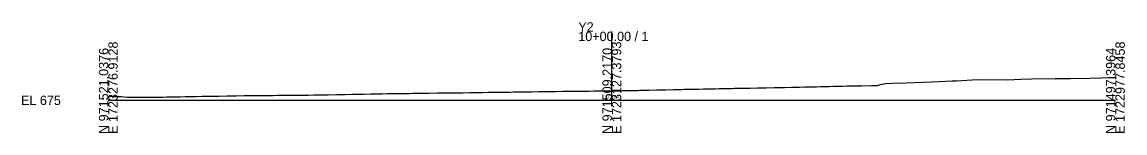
# Model space of a CAD drawing. Extents: x -26 to 303, y -10 to 3067.
# Drawn here: x -25.7 to 302.8, y -9.7 to 23.3 of the extents above; entities that cross this region are included whole.
import ezdxf

# ---------------------------------------------------------------- set-up
doc = ezdxf.new("R2010")
doc.units = 0
for name, color, linetype in [('Default', 7, 'Continuous'), ('Exist 6 AWG with gnd feeder circuit', 7, 'Continuous'), ('Exist 6 AWG with gnd feeder circuit in conduit', 7, 'Continuous'), ('Prop DSN Text', 7, 'Continuous')]:
    doc.layers.add(name, color=color, linetype=linetype)

msp = doc.modelspace()

# ---------------------------------------------------------------- linework, layer by layer
at = {"layer": 'Exist 6 AWG with gnd feeder circuit'}
msp.add_lwpolyline([(0, 1.19), (1.4, 1.17), (1.98, 1.15), (3.41, 1.11), (3.79, 1.09), (5.57, 0.97), (7.03, 0.95), (8.11, 0.94), (8.85, 0.94), (9.82, 0.93), (10.57, 0.93), (11.19, 0.91), (13.95, 0.94), (14.3, 0.96), (16.32, 0.97), (17.38, 0.99), (19.23, 1.02), (20.43, 1.05), (21.41, 1.07), (22.88, 1.1), (24.45, 1.13), (25.41, 1.14), (26.22, 1.15), (27.94, 1.19), (29.92, 1.22), (30.43, 1.23), (32.61, 1.26), (32.92, 1.27), (35.41, 1.32), (36.49, 1.33), (38.08, 1.36), (40.47, 1.39), (42.47, 1.41), (42.94, 1.42), (43.49, 1.43), (45.46, 1.45), (47.14, 1.46), (47.99, 1.47), (48.96, 1.48), (50.46, 1.5), (51.79, 1.51), (52.99, 1.52), (54.11, 1.53), (55.5, 1.55), (55.91, 1.55), (57.39, 1.56), (58.43, 1.57), (59.68, 1.58), (61.19, 1.6), (63, 1.62), (63.4, 1.63), (63.97, 1.63), (65.53, 1.65), (68.04, 1.69), (68.5, 1.7), (70.55, 1.74), (72.72, 1.8), (73.04, 1.81), (73.42, 1.81), (75.55, 1.86), (76.15, 1.87), (78.06, 1.89), (79.7, 1.93), (80.56, 1.95), (81.58, 1.97), (83.07, 2), (84.33, 2.01), (85.58, 2.03), (87.04, 2.05), (88.09, 2.06), (89.75, 2.08), (90.6, 2.09), (91.32, 2.1), (93.1, 2.12), (93.63, 2.13), (95.61, 2.16), (98.11, 2.19), (100.65, 2.21), (103.39, 2.24), (105.63, 2.27), (107.56, 2.29), (108.13, 2.3), (109.9, 2.32), (110.65, 2.34), (111.53, 2.35), (113.15, 2.38), (114.27, 2.39), (115.65, 2.41), (116.85, 2.42), (118.17, 2.44), (119.68, 2.47), (120.66, 2.48), (121.5, 2.49), (123.23, 2.52), (123.85, 2.53), (125.73, 2.57), (126.18, 2.57), (128.21, 2.6), (130.79, 2.63), (131.48, 2.64), (133.2, 2.66), (135.4, 2.69), (135.71, 2.7), (137.76, 2.72), (138.23, 2.72), (138.82, 2.73), (140.78, 2.74), (141.59, 2.75), (143.27, 2.77), (144.71, 2.78), (145.74, 2.79), (146.97, 2.8), (148.27, 2.82), (150, 2.84), (150.8, 2.85), (152.48, 2.87), (153.31, 2.88), (154.03, 2.9), (155.77, 2.93), (157.86, 2.97), (158.3, 2.98), (161.01, 3.03), (163.35, 3.1), (166.02, 3.16), (168.33, 3.21), (168.78, 3.22), (170.87, 3.27), (171.53, 3.28), (173.38, 3.31), (174.94, 3.34), (175.85, 3.36), (177.28, 3.38), (178.38, 3.41), (179.59, 3.43), (180.9, 3.46), (181.94, 3.48), (183.38, 3.5), (185.11, 3.54), (185.9, 3.56), (186.57, 3.57), (188.43, 3.6), (188.92, 3.61), (190.91, 3.65), (191.23, 3.66), (193.53, 3.7), (195.36, 3.73), (195.95, 3.75), (198.42, 3.8), (200.54, 3.84), (200.94, 3.85), (201.42, 3.86), (203.48, 3.9), (205.17, 3.92), (205.94, 3.93), (207.51, 3.97), (208.45, 3.98), (209.83, 4.02), (210.99, 4.05), (212.17, 4.08), (213.45, 4.11), (214.59, 4.16), (215.92, 4.19), (217.54, 4.23), (218.73, 4.25), (220.08, 4.28), (221.12, 4.31), (221.73, 4.32), (224.39, 4.36), (227.33, 4.41), (228.39, 4.43), (229.17, 4.45), (230.06, 4.66), (231.53, 5), (233.69, 5.07), (237.71, 5.21), (245.18, 5.54), (247.46, 5.62), (251.4, 5.78), (252.71, 5.83), (258.87, 6.17), (267.84, 6.11), (271.81, 6.28), (274.96, 6.37), (282.09, 6.46), (286.58, 6.53), (292.47, 6.64), (295.7, 6.7), (297.81, 6.77), (300, 6.81)], dxfattribs=at)
at = {"layer": 'Prop DSN Text'}
for p, q in [((150, 0), (150, 20.43)), ((0, 0), (150, 0)), ((150, 0), (300, 0))]:
    msp.add_line(p, q, dxfattribs=at)

# ---------------------------------------------------------------- texts
at = {"layer": 'Default'}
msp.add_text('-', height=0.0001, dxfattribs=at).set_placement((0, 0))
at = {"layer": 'Exist 6 AWG with gnd feeder circuit in conduit'}
msp.add_text('677.84', height=1, dxfattribs=at).set_placement((147.85, 0.55))
at = {"layer": 'Prop DSN Text'}
for s, p in [('Y2', (140, 20.43)), ('10+00.00 / 1', (140, 17.63)), ('EL 675', (-26, -1.4))]:
    msp.add_text(s, height=2.8, dxfattribs=at).set_placement(p)
for s, p in [('E 1723276.9128', (2.8, -10)), ('E 1723127.3793', (152.8, -10)), ('E 1722977.8458', (302.8, -10)), ('N 971521.0376', (0, -10)), ('N 971509.2170', (150, -10)), ('N 971497.3964', (300, -10))]:
    msp.add_text(s, height=2.8, rotation=90, dxfattribs=at).set_placement(p)

doc.saveas('drawing.dxf')
